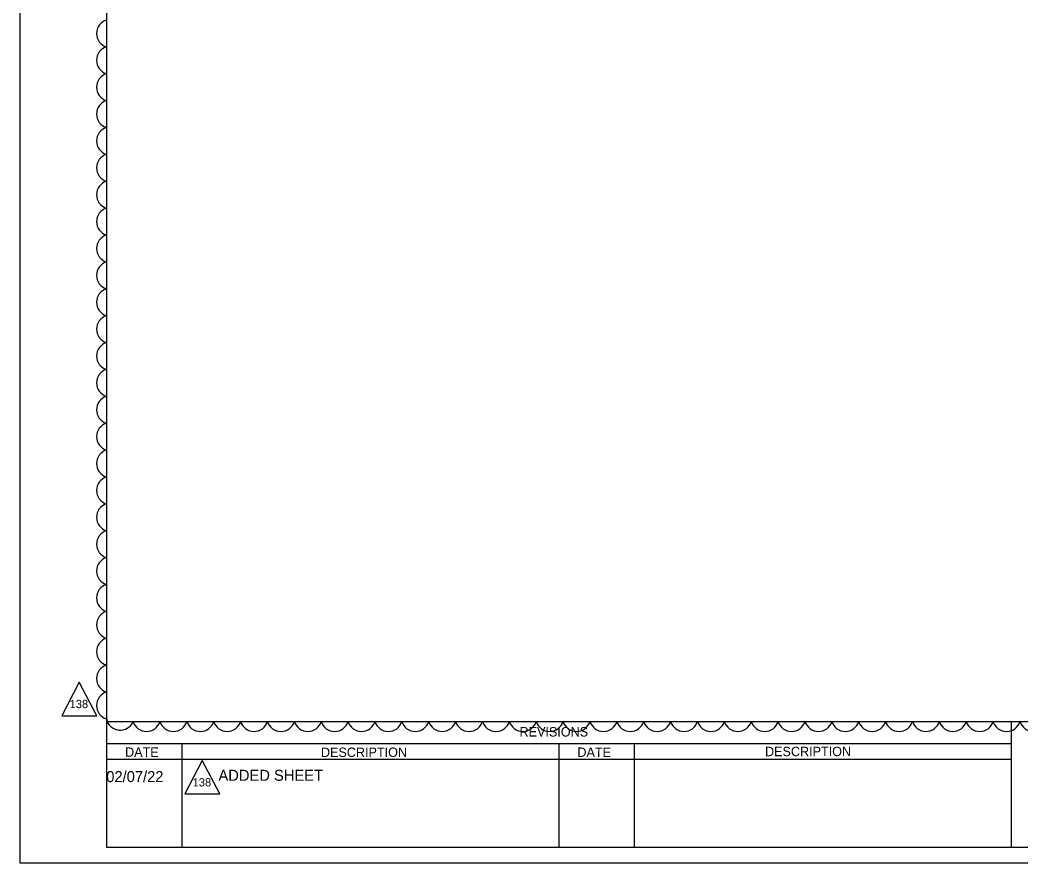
# Model space of a CAD drawing. Extents: x -811.3 to -790.1, y -2211.9 to -2188.9.
# Drawn here: x -811.34 to -804.97, y -2199.5 to -2194.13 of the extents above; entities that cross this region are included whole.
import ezdxf

# ---------------------------------------------------------------- set-up
doc = ezdxf.new("R2010")
doc.units = 0
for name, color, linetype in [('AdhocPoint_dp', 7, 'Continuous'), ('Cloud_dp', 7, 'Continuous'), ('PlotBorder_dp', 7, 'Continuous'), ('SheetBorder_dp', 7, 'Continuous'), ('SheetLines_dp', 7, 'Continuous'), ('TextLabel', 7, 'Continuous'), ('TextMisc', 7, 'Continuous')]:
    doc.layers.add(name, color=color, linetype=linetype)

msp = doc.modelspace()

# ---------------------------------------------------------------- linework, layer by layer
at = {"layer": 'AdhocPoint_dp'}
msp.add_line((-811.3358, -2199.5006), (-811.3358, -2199.5006), dxfattribs=at)
msp.add_line((-811.3358, -2199.5006), (-811.3358, -2199.5006), dxfattribs=at)
at = {"layer": 'Cloud_dp'}
for points in [[(-810.9581, -2198.3492), (-811.069, -2198.5629), (-810.8472, -2198.5629)], [(-810.1749, -2198.8478), (-810.2858, -2199.0614), (-810.064, -2199.0614)]]:
    msp.add_lwpolyline(points, close=True, dxfattribs=at)
for centre, radius, start, end in [((-810.7588, -2194.2199), 0.0897, 107.5, 252.5), ((-810.7588, -2194.391), 0.0897, 107.5, 252.5), ((-810.7588, -2194.5621), 0.0897, 107.5, 252.5), ((-810.7588, -2194.7332), 0.0897, 107.5, 252.5), ((-810.7588, -2194.9044), 0.0897, 107.5, 252.5), ((-810.7588, -2195.0755), 0.0897, 107.5, 252.5), ((-810.7588, -2195.2466), 0.0897, 107.5, 252.5), ((-810.7588, -2195.4177), 0.0897, 107.5, 252.5), ((-810.7588, -2195.5889), 0.0897, 107.5, 252.5), ((-810.7588, -2195.76), 0.0897, 107.5, 252.5), ((-810.7588, -2195.9311), 0.0897, 107.5, 252.5), ((-810.7588, -2196.1022), 0.0897, 107.5, 252.5), ((-810.7588, -2196.2733), 0.0897, 107.5, 252.5), ((-810.7588, -2196.4445), 0.0897, 107.5, 252.5), ((-810.7588, -2196.6156), 0.0897, 107.5, 252.5), ((-810.7588, -2196.7867), 0.0897, 107.5, 252.5), ((-810.7588, -2196.9578), 0.0897, 107.5, 252.5), ((-810.7588, -2197.129), 0.0897, 107.5, 252.5), ((-810.7588, -2197.3001), 0.0897, 107.5, 252.5), ((-810.7588, -2197.4712), 0.0897, 107.5, 252.5), ((-810.7588, -2197.6423), 0.0897, 107.5, 252.5), ((-810.7588, -2197.8134), 0.0897, 107.5, 252.5), ((-810.7588, -2197.9846), 0.0897, 107.5, 252.5), ((-810.7588, -2198.1557), 0.0897, 107.5, 252.5), ((-810.7588, -2198.3268), 0.0897, 107.5, 252.5), ((-810.7588, -2198.4979), 0.0897, 107.5, 252.5), ((-810.698, -2198.5653), 0.0896, 191.74536, 336.74536), ((-810.5301, -2198.5737), 0.0897, 197.5, 342.5), ((-810.359, -2198.5737), 0.0897, 197.5, 342.5), ((-810.1879, -2198.5737), 0.0897, 197.5, 342.5), ((-810.0167, -2198.5737), 0.0897, 197.5, 342.5), ((-809.8456, -2198.5737), 0.0897, 197.5, 342.5), ((-809.6745, -2198.5737), 0.0897, 197.5, 342.5), ((-809.5034, -2198.5737), 0.0897, 197.5, 342.5), ((-809.3323, -2198.5737), 0.0897, 197.5, 342.5), ((-809.1611, -2198.5737), 0.0897, 197.5, 342.5), ((-808.99, -2198.5737), 0.0897, 197.5, 342.5), ((-808.8189, -2198.5737), 0.0897, 197.5, 342.5), ((-808.6478, -2198.5737), 0.0897, 197.5, 342.5), ((-808.4766, -2198.5737), 0.0897, 197.5, 342.5), ((-808.3055, -2198.5737), 0.0897, 197.5, 342.5), ((-808.1344, -2198.5737), 0.0897, 197.5, 342.5), ((-807.9633, -2198.5737), 0.0897, 197.5, 342.5), ((-807.7921, -2198.5737), 0.0897, 197.5, 342.5), ((-807.621, -2198.5737), 0.0897, 197.5, 342.5), ((-807.4499, -2198.5737), 0.0897, 197.5, 342.5), ((-807.2788, -2198.5737), 0.0897, 197.5, 342.5), ((-807.1077, -2198.5737), 0.0897, 197.5, 342.5), ((-806.9365, -2198.5737), 0.0897, 197.5, 342.5), ((-806.7654, -2198.5737), 0.0897, 197.5, 342.5), ((-806.5943, -2198.5737), 0.0897, 197.5, 342.5), ((-806.4232, -2198.5737), 0.0897, 197.5, 342.5), ((-806.252, -2198.5737), 0.0897, 197.5, 342.5), ((-806.0809, -2198.5737), 0.0897, 197.5, 342.5), ((-805.9098, -2198.5737), 0.0897, 197.5, 342.5), ((-805.7387, -2198.5737), 0.0897, 197.5, 342.5), ((-805.5676, -2198.5737), 0.0897, 197.5, 342.5), ((-805.3964, -2198.5737), 0.0897, 197.5, 342.5), ((-805.2253, -2198.5737), 0.0897, 197.5, 342.5), ((-805.0542, -2198.5737), 0.0897, 197.5, 342.5), ((-804.8831, -2198.5737), 0.0897, 197.5, 342.5)]:
    msp.add_arc(centre, radius, start, end, dxfattribs=at)
at = {"layer": 'PlotBorder_dp'}
msp.add_lwpolyline([(-811.3358, -2199.5006), (-794.8358, -2199.5006), (-794.8358, -2188.9006), (-811.3358, -2188.9006)], close=True, dxfattribs=at)
at = {"layer": 'SheetBorder_dp'}
for p, q in [((-810.7858, -2189.0006), (-810.7858, -2199.4006)), ((-810.7858, -2198.6006), (-795.3858, -2198.6006)), ((-810.7858, -2199.4006), (-795.3858, -2199.4006))]:
    msp.add_line(p, q, dxfattribs=at)
at = {"layer": 'SheetLines_dp'}
for p, q in [((-805.0258, -2198.6006), (-805.0258, -2199.4006)), ((-810.7858, -2198.7406), (-805.0258, -2198.7406)), ((-810.3058, -2198.7406), (-810.3058, -2199.4006)), ((-807.9058, -2198.7406), (-807.9058, -2199.4006)), ((-807.4258, -2198.7406), (-807.4258, -2199.4006)), ((-810.7858, -2198.8406), (-805.0258, -2198.8406))]:
    msp.add_line(p, q, dxfattribs=at)

# ---------------------------------------------------------------- texts
at = {"layer": 'Cloud_dp'}
for p in [(-811.0193, -2198.5147), (-810.2361, -2199.0133)]:
    msp.add_text('138', height=0.0525, rotation=360, dxfattribs=at).set_placement(p)
at = {"layer": 'TextLabel'}
for s, p in [('02/07/22', (-810.7866, -2198.9855)), ('ADDED SHEET', (-810.0721, -2198.9774))]:
    msp.add_text(s, height=0.07, rotation=0, dxfattribs=at).set_placement(p)
at = {"layer": 'TextMisc'}
msp.add_text('REVISIONS', height=0.06, dxfattribs=at).set_placement((-808.1553, -2198.6955))
for s, rotation, p in [('DATE', 359.86925, (-810.6668, -2198.8247)), ('DESCRIPTION', 0.04975, (-809.4198, -2198.8259)), ('DESCRIPTION', 0.04975, (-806.5922, -2198.8209)), ('DATE', 359.86925, (-807.7868, -2198.8253))]:
    msp.add_text(s, height=0.06, rotation=rotation, dxfattribs=at).set_placement(p)

doc.saveas('drawing.dxf')
